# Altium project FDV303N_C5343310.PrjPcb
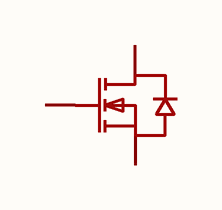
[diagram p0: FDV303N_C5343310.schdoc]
1 sheet, 1 parts. Net scope: global (net labels, ports and power ports of the same name join across sheets).

## Sheet FDV303N_C5343310.schdoc
size 127 x 101 mm

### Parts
Q?  fdv303n_c5343310  [SOT-23-3_L2.9-W1.3-P1.90-LS2.4-BR]  (value not drawn)

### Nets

Not connected (* = marked no-connect by the designer): Q? 1(G) 2(S) 3(D)

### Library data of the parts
Q? = fdv303n_c5343310: 数量:1个N沟道;漏源电压(Vdss):30V;连续漏极电流(Id):2A;导通电阻(RDS(on)):200mΩ@4.5V;耗散功率(Pd):1W;阈值电压(Vgs(th)):800mV;; Manufacturer: MSKSEMI(美森科); AddInBom: yes; ModelId: c62791f0466c4ae2a892c056b845b0ca; ModelName: SOT-23-3P_L2.9-W1.3-H1.0-LS2.4-P0.95; ModelTransform: 98.425,114.173,0,180,0,0,0.0005,-0.0005,0; Number: 1个N沟道; Drain to Source Voltage: 30V; Current - Continuous Drain(Id): 2A; Pd - Power Dissipation: 1W; Gate Threshold Voltage (Vgs(th)): 800mV; Gate Charge(Qg): 8.4nC@4.5V; Input Capacitance(Ciss): 695pF; Reverse Transfer Capacitance (Crss@Vds): 36pF; Type: N沟道; Output Capacitance(Coss): 45pF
